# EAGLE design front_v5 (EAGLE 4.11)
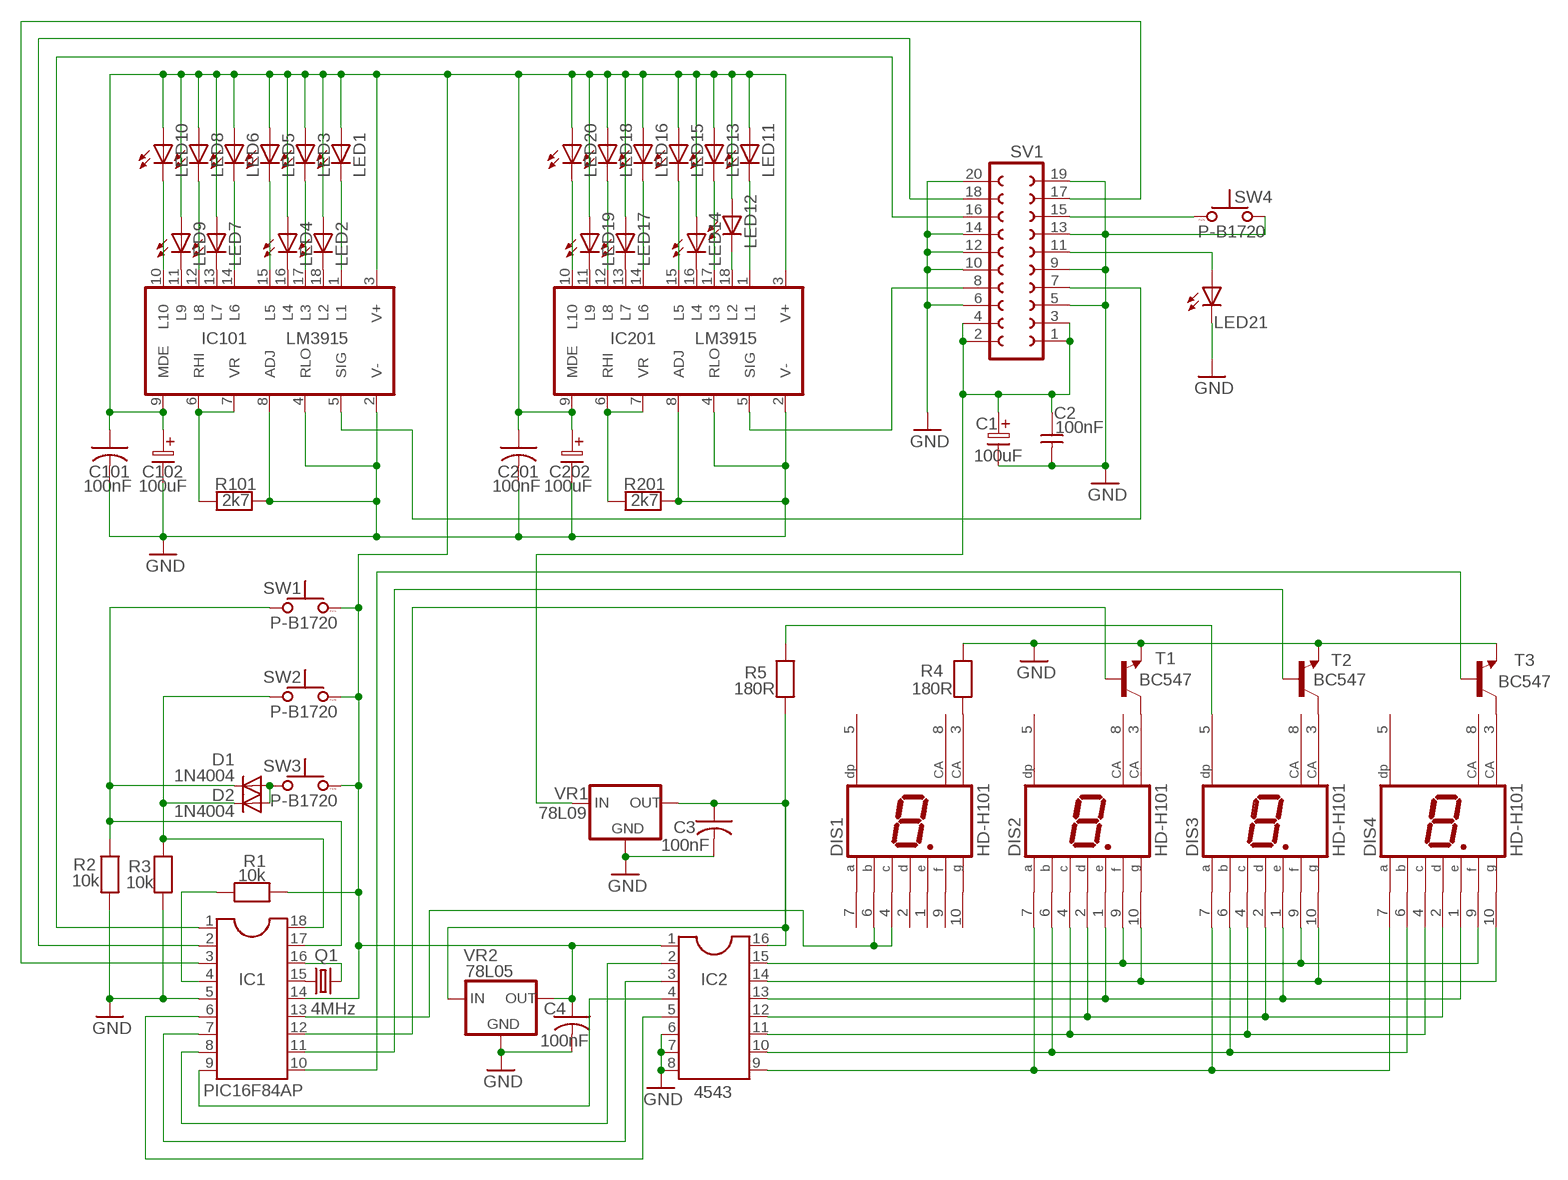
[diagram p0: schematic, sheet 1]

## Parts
C1  100uF  ELC-2,5  [ES-2,5]
C2  100nF  CAPNP-5  [C-5]
C3  100nF  CAP-5  [C-5]
C4  100nF  CAP-5  [C-5]
C101  100nF  CAP-5  [C-5]
C102  100uF  ELC-2,5  [ES-2,5]
C201  100nF  CAP-5  [C-5]
C202  100uF  ELC-2,5  [ES-2,5]
D1  1N4004  [DO41-10]
D2  1N4004  [DO41-10]
DIS1  HD-H101  [HDSP-M]
DIS2  HD-H101  [HDSP-M]
DIS3  HD-H101  [HDSP-M]
DIS4  HD-H101  [HDSP-M]
IC1  PIC16F84AP  DIL18  [DIL18]
IC2  4543  DIL16  [DIL16]
IC101  LM3915  LM3914N  [DIL18]
IC201  LM3915  LM3914N  [DIL18]
LED1  LED5MM  [LED5MM]
LED2  LED5MM  [LED5MM]
LED3  LED5MM  [LED5MM]
LED4  LED5MM  [LED5MM]
LED5  LED5MM  [LED5MM]
LED6  LED5MM  [LED5MM]
LED7  LED5MM  [LED5MM]
LED8  LED5MM  [LED5MM]
LED9  LED5MM  [LED5MM]
LED10  LED5MM  [LED5MM]
LED11  LED5MM  [LED5MM]
LED12  LED5MM  [LED5MM]
LED13  LED5MM  [LED5MM]
LED14  LED5MM  [LED5MM]
LED15  LED5MM  [LED5MM]
LED16  LED5MM  [LED5MM]
LED17  LED5MM  [LED5MM]
LED18  LED5MM  [LED5MM]
LED19  LED5MM  [LED5MM]
LED20  LED5MM  [LED5MM]
LED21  LED5MM  [LED5MM]
Q1  4MHz  CRYTALHC49U-V  [HC49U-V]
R1  10k  RESEU-7,5  [R-7,5]
R2  10k  RESEU-7,5  [R-7,5]
R3  10k  RESEU-7,5  [R-7,5]
R4  180R  RESEU-7,5  [R-7,5]
R5  180R  RESEU-7,5  [R-7,5]
R101  2k7  RESEU-7,5  [R-7,5]
R201  2k7  RESEU-7,5  [R-7,5]
SV1  FE10-2  [FE10-2]
SW1  P-B1720  [P-B1720]
SW2  P-B1720  [P-B1720]
SW3  P-B1720  [P-B1720]
SW4  P-B1720  [P-B1720]
T1  BC547  BC238  [TO92]
T2  BC547  BC238  [TO92]
T3  BC547  BC238  [TO92]
VR1  78L09  78LXX  [78LXX]
VR2  78L05  78LXX  [78LXX]

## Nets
GND: C1.2 C2.2 C3.2 C4.2 C101.2 C102.2 C201.2 C202.2 IC1.5 IC2.6 IC2.7 IC2.8 IC101.2(V-) IC101.4(RLO) IC101.8(ADJ) IC201.2(V-) IC201.4(RLO) IC201.8(ADJ) LED21.K(C) R2.1 R3.1 R4.2 R101.2 R201.2 SV1.5 SV1.6 SV1.9 SV1.10 SV1.12 SV1.13 SV1.14 SV1.19 SV1.20 SW4.2 T1.1(E) T2.1(E) T3.1(E) VR1.GND VR2.GND
N$1: IC1.4 R1.1
N$2: IC1.15 Q1.1
N$3: IC1.16 Q1.2
N$4: DIS1.3(CA) R4.1
N$5: IC1.6 IC2.5
N$6: IC1.7 IC2.3
N$7: IC1.8 IC2.2
N$8: IC1.9 IC2.4
N$9: C3.1 IC2.16 R5.1 VR1.OUT VR2.IN
N$11: LED21.A SV1.11
N$12: C1.1 C2.1 SV1.1 SV1.2 SV1.3 SV1.4 VR1.IN
N$13: DIS2.7(A) DIS3.7(A) DIS4.7(A) IC2.9
N$14: DIS2.6(B) DIS3.6(B) DIS4.6(B) IC2.10
N$15: DIS2.4(C) DIS3.4(C) DIS4.4(C) IC2.11
N$16: DIS2.2(D) DIS3.2(D) DIS4.2(D) IC2.12
N$17: DIS2.1(E) DIS3.1(E) DIS4.1(E) IC2.13
N$18: DIS2.10(G) DIS3.10(G) DIS4.10(G) IC2.14
N$19: DIS2.9(F) DIS3.9(F) DIS4.9(F) IC2.15
N$20: DIS1.4(C) DIS1.6(B) IC1.13
N$21: DIS3.5(DP) R5.2
N$22: DIS2.3(CA) T1.3(C)
N$23: DIS3.3(CA) T2.3(C)
N$24: DIS4.3(CA) T3.3(C)
N$25: IC1.12 T1.2(B)
N$27: IC1.11 T2.2(B)
N$28: IC1.10 T3.2(B)
N$29: SV1.15 SW4.1
N$30: D1.C IC1.17 R2.2 SW1.2
N$31: D2.C IC1.18 R3.2 SW2.2
N$32: IC1.1 SV1.16
N$33: IC1.2 SV1.18
N$34: IC1.3 SV1.17
N$35: IC201.1(L1) LED11.K(C)
N$36: IC101.18(L2) LED2.K(C)
N$37: IC201.17(L3) LED13.K(C)
N$38: IC101.16(L4) LED4.K(C)
N$39: IC201.15(L5) LED15.K(C)
N$40: IC201.14(L6) LED16.K(C)
N$41: IC101.13(L7) LED7.K(C)
N$42: IC201.12(L8) LED18.K(C)
N$43: IC101.11(L9) LED9.K(C)
N$44: IC201.10(L10) LED20.K(C)
N$45: IC201.6(RHI) IC201.7(VR) R201.1
N$47: IC201.16(L4) LED14.K(C)
N$48: IC201.13(L7) LED17.K(C)
N$49: IC201.11(L9) LED19.K(C)
N$50: IC201.5(SIG) SV1.8
N$51: IC101.5(SIG) SV1.7
N$52: IC201.18(L2) LED12.K(C)
N$55: D1.A D2.A SW3.2
N$76: IC101.1(L1) LED1.K(C)
N$80: IC101.17(L3) LED3.K(C)
N$83: IC101.15(L5) LED5.K(C)
N$84: IC101.14(L6) LED6.K(C)
N$86: IC101.12(L8) LED8.K(C)
N$88: IC101.10(L10) LED10.K(C)
N$93: IC101.6(RHI) IC101.7(VR) R101.1
V+: C4.1 C101.1 C102.1 C201.1 C202.1 IC1.14 IC2.1 IC101.3(V+) IC101.9(MDE) IC201.3(V+) IC201.9(MDE) LED1.A LED2.A LED3.A LED4.A LED5.A LED6.A LED7.A LED8.A LED9.A LED10.A LED11.A LED12.A LED13.A LED14.A LED15.A LED16.A LED17.A LED18.A LED19.A LED20.A R1.2 SW1.1 SW2.1 SW3.1 VR2.OUT
Unconnected: DIS1.1(E) DIS1.2(D) DIS1.5(DP) DIS1.7(A) DIS1.8(CA) DIS1.9(F) DIS1.10(G) DIS2.5(DP) DIS2.8(CA) DIS3.8(CA) DIS4.5(DP) DIS4.8(CA) SW1.3 SW1.4 SW2.3 SW2.4 SW3.3 SW3.4 SW4.3 SW4.4

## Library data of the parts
C1 C102 C202 = discrete:ELC-2,5
C2 = discrete:CAPNP-5
C3 C4 C101 C201 = discrete:CAP-5
D1 D2 = diode:1N4004: DIODE
DIS1-DIS4 = display-hp:HD-H101: LED DISPLAY 1-character 7 segment, decimal point right
IC1 = ic-package:DIL18: Dual In Line
IC2 = ic-package:DIL16: Dual In Line
IC101 IC201 = linear:LM3914N: LED DRIVER senses analog voltage levels and drives 10 LEDs
LED1-LED21 = led:LED: LED
Q1 = crystal:CRYTAL: CRYSTAL
R1-R5 R101 R201 = discrete:RESEU-7,5
SV1 = con-lsta:FE10-2: FEMALE HEADER
SW1-SW4 = #PaJa_16:P-B1720: &micro;-tlacitko
T1-T3 = transistor:BC238: NPN TRANSISTOR
VR1 VR2 = v-reg:78LXX: VOLTAGE REGULATOR

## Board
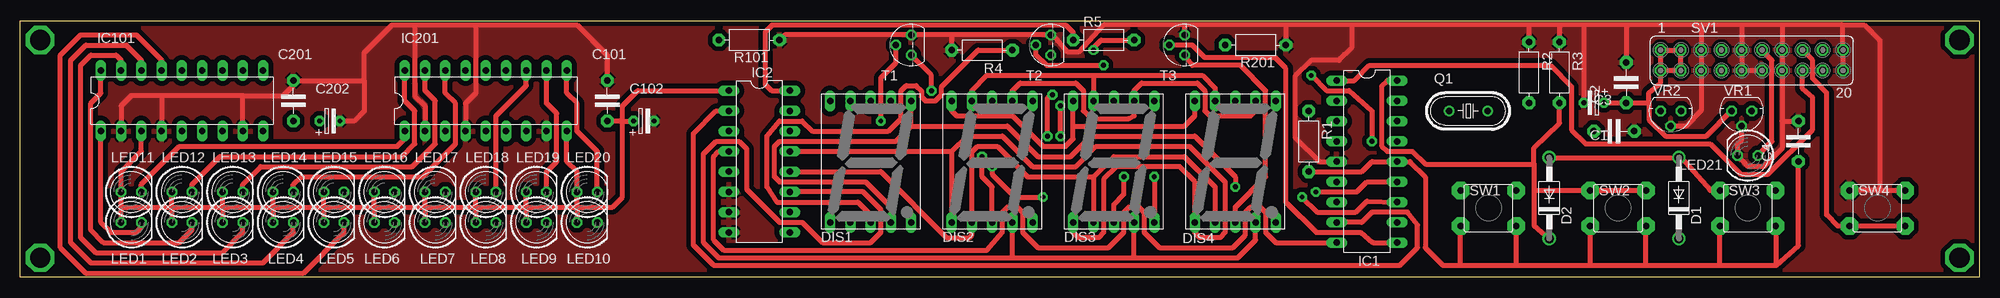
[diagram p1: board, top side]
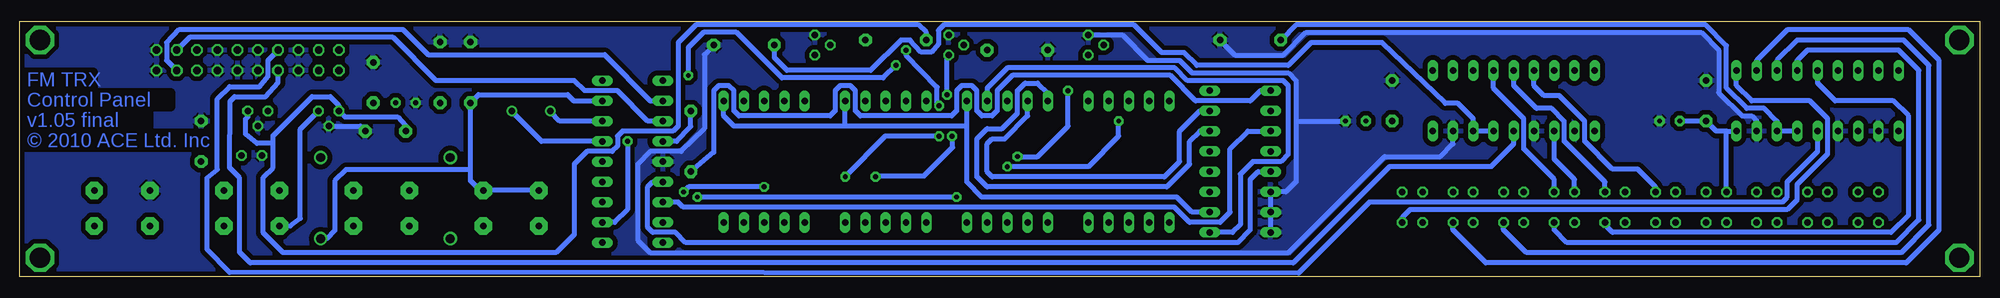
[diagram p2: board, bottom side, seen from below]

Size 245.72 x 32.05 mm. Coordinates in mm from the lower left corner, seen from the top.
Outline: 0,0 245.72,0 245.72,32.05 0,32.05 0,0
Copper layers (1*16): Top 0.035mm / dielectric 1.5mm / Bottom 0.035mm
Design rules "TRIDA5": minimum track width 10mil, minimum drill 24mil, track to track 12mil, track to pad 10mil, pad to pad 11mil, via to via 12mil, smd to smd 12mil, copper to edge 25mil, drill to drill 12mil, minimum pad ring 10mil, minimum via ring 12mil, stop-mask expansion 4mil, vias tented up to drill 0mil, thermal gap 10mil

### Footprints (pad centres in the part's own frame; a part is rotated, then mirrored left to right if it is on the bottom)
ES-2,5 = drill 0.61 pad 1.27 octagon: 1 -1.27,0; 2 1.27,0
C-5 = drill 0.813 pad 1.6 octagon: 1 -2.54,0; 2 2.54,0
DO41-10 = drill 1.118 round: A 5.08,0; C -5.08,0
HDSP-M = drill 0.813 long: 1 -5.08,-7.62; 2 -2.54,-7.62; 3 0,-7.62; 4 2.54,-7.62; 5 5.08,-7.62; 6 5.08,7.62; 7 2.54,7.62; 8 0,7.62; 9 -2.54,7.62; 10 -5.08,7.62
DIL18 = drill 0.813 long: 1 -10.16,-3.81; 2 -7.62,-3.81; 3 -5.08,-3.81; 4 -2.54,-3.81; 5 0,-3.81; 6 2.54,-3.81; 7 5.08,-3.81; 8 7.62,-3.81; 9 10.16,-3.81; 10 10.16,3.81; 11 7.62,3.81; 12 5.08,3.81; 13 2.54,3.81; 14 0,3.81; 15 -2.54,3.81; 16 -5.08,3.81; 17 -7.62,3.81; 18 -10.16,3.81
DIL16 = drill 0.813 long: 1 -8.89,-3.81; 2 -6.35,-3.81; 3 -3.81,-3.81; 4 -1.27,-3.81; 5 1.27,-3.81; 6 3.81,-3.81; 7 6.35,-3.81; 8 8.89,-3.81; 9 8.89,3.81; 10 6.35,3.81; 11 3.81,3.81; 12 1.27,3.81; 13 -1.27,3.81; 14 -3.81,3.81; 15 -6.35,3.81; 16 -8.89,3.81
LED5MM = drill 0.813 octagon: A -1.27,0; K 1.27,0
HC49U-V = drill 0.813 round: 1 -2.413,0; 2 2.413,0
R-7,5 = drill 0.813 pad 1.6 octagon: 1 -3.81,0; 2 3.81,0
FE10-2 = drill 0.914 octagon: 1 -11.43,1.27; 2 -11.43,-1.27; 3 -8.89,1.27; 4 -8.89,-1.27; 5 -6.35,1.27; 6 -6.35,-1.27; 7 -3.81,1.27; 8 -3.81,-1.27; 9 -1.27,1.27; 10 -1.27,-1.27; 11 1.27,1.27; 12 1.27,-1.27; 13 3.81,1.27; 14 3.81,-1.27; 15 6.35,1.27; 16 6.35,-1.27; 17 8.89,1.27; 18 8.89,-1.27; 19 11.43,1.27; 20 11.43,-1.27
P-B1720 = drill 0.813 pad 2.184 octagon: 1 -3.493,-2.223; 2 -3.493,2.223; 3 3.493,-2.223; 4 3.493,2.223
TO92 = drill 0.813 octagon: 1 1.27,0; 2 0,1.905; 3 -1.27,0
78LXX = drill 0.813 octagon: GND 0,1.905; IN 1.27,0; OUT -1.27,0

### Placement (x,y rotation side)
C1  197.35,21.81 180 top
C2  201.42,24.35 90 top
C3  199.89,18.25 0 top
C4  223.01,16.98 90 top
C101  73.66,22.06 90 top
C102  78.23,19.52 0 top
C201  34.29,22.06 90 top
C202  38.86,19.52 0 top
D1  208.02,9.87 90 top
D2  191.76,9.87 90 top
DIS1  106.67,14.44 0 top
DIS2  121.92,14.44 0 top
DIS3  137.15,14.44 0 top
DIS4  152.39,14.44 0 top
IC1  168.9,14.44 270 top
IC2  92.7,14.44 270 top
IC101  20.32,22.06 0 top
IC201  58.41,22.06 0 top
LED1  13.96,6.82 0 top
LED2  20.32,6.82 0 top
LED3  26.66,6.82 0 top
LED4  33.02,6.82 0 top
LED5  39.37,6.82 0 top
LED6  45.72,6.82 0 top
LED7  52.06,6.82 0 top
LED8  58.41,6.82 0 top
LED9  64.77,6.82 0 top
LED10  71.11,6.82 0 top
LED11  13.96,10.63 0 top
LED12  20.32,10.63 0 top
LED13  26.66,10.63 0 top
LED14  33.02,10.63 0 top
LED15  39.37,10.63 0 top
LED16  45.72,10.63 0 top
LED17  52.06,10.63 0 top
LED18  58.41,10.63 0 top
LED19  64.77,10.63 0 top
LED20  71.11,10.63 0 top
LED21  216.66,15.2 180 top
Q1  181.6,20.79 180 top
R1  161.6,16.98 270 top
R2  189.22,25.62 270 top
R3  193.03,25.62 270 top
R4  120.64,28.41 180 top
R5  135.88,29.68 0 top
R101  91.44,29.68 0 top
R201  154.93,29.04 0 top
SV1  217.16,27.14 0 top
SW1  184.14,8.6 0 top
SW2  200.4,8.6 0 top
SW3  216.66,8.6 0 top
SW4  232.91,8.6 0 top
T1  111.75,29.04 90 top
T2  129.28,29.04 90 top
T3  146.04,29.04 90 top
VR1  215.89,20.79 180 top
VR2  207,20.79 180 top

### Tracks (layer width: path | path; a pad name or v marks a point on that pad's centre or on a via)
GND
  Top 0.61: 220.97,31.58 215.89,31.58 | 215.89,31.58 210.81,31.58 | 228.59,31.58 220.97,31.58 | 233.23,10.82 233.23,29.62 231.26,31.58 228.59,31.58 | VR1.GND 215.89,17.17 215.39,16.66 LED21.K 216.72,13.81 218.69,13.81 220.97,16.09 220.97,19.52 | VR2.GND 208.91,18.88 210.81,20.85 SV1.6 SV1.5 210.81,31.58 | 210.81,31.58 201.42,31.58 | 201.42,31.58 196.08,31.58 | 196.08,31.58 193.03,31.58 | 193.03,31.58 189.22,31.58 | 189.22,31.58 167,31.58 | 167,31.58 158.68,31.58 | 158.68,31.58 146.04,31.58 | 146.04,31.58 T3.1 | IC1.5 163,14.44 159.89,17.49 159.89,25.14 161.92,27.14 165.41,27.14 167,28.73 167,31.58 | 146.04,31.58 135.88,31.58 132.71,28.16 131.44,28.16 129.53,30.31 | 129.53,30.31 T2.1 | 129.53,30.31 116.83,30.31 | 116.83,30.31 111.95,30.31 | 111.95,30.31 T1.1 | 189.22,31.58 R2.1 | 193.03,31.58 R3.1 | 116.83,30.31 R4.2 | 220.97,19.52 SV1.14 SV1.13 220.97,31.58 | SV1.10 215.89,25.74 | SV1.10 SV1.9 215.89,31.58 | SV1.20 SV1.19 228.59,31.58 | IC101.2 12.7,21.42 13.96,22.7 17.78,22.7 | 17.78,22.7 IC101.4 | 43.17,24.6 C201.2 34.29,23.96 33.02,22.7 27.94,22.7 | 27.94,22.7 17.78,22.7 | 57.15,31.58 69.84,31.58 73.66,27.77 C101.2 | 49.52,31.58 57.15,31.58 | 49.52,31.58 46.67,31.58 43.17,28.09 43.17,24.6 | IC201.4 55.88,21.74 57.15,23.01 57.15,31.58 | IC201.2 50.8,21.42 49.52,22.7 49.52,31.58 | 158.68,31.58 158.74,31.52 R201.2 | 43.17,24.6 43.17,20.79 41.91,19.52 C202.2 | 111.95,30.31 95.88,30.31 R101.2 | 196.08,31.58 C1.2 | 201.42,31.58 C2.2 | 220.97,19.52 C4.2 | 233.23,10.82 SW4.2 | 233.23,10.82 236.28,10.82 | SV1.10 SV1.12 | IC101.8 27.94,22.7
  Bottom 0.61: 85.72,19.52 85.72,11.9 86.99,10.63 IC2.6 IC2.7 IC2.8 | 85.72,19.52 85.72,24.6 86.67,25.55 98.74,25.55 100.33,27.14 104.33,27.14 107.5,30.31 111.63,30.31 111.75,30.19 T1.1 | IC201.8 66.03,16.66 67.62,15.08 74.61,15.08 86.67,3.01 166.68,3.01 168.27,4.6 168.27,14.12 166.68,15.71 162.81,15.71 159.89,18.57 159.89,27.84 R201.2 | R101.2 93.34,27.77 87.31,27.77 84.45,30.63 34.92,30.63 32.7,28.41 32.7,23.08 29.78,20.15 28.57,20.15 27.94,19.52 IC101.8 | 85.72,19.52 C102.2 | VR2.GND 203,18.88 C3.2
  pour Bottom (isolate 0.61): -0.01,31.97 245.61,31.97 245.61,-0.04 -0.01,-0.04
  pour Top (isolate 0.61): -0.01,31.97 -0.01,0.22 245.61,0.22 245.61,31.97
N$1
  Bottom 0.61: R1.1 161.6,18.82 163.38,16.98 IC1.4
N$2
  Bottom 0.61: IC1.15 180.33,16.98 184.02,20.66 Q1.1
N$3
  Bottom 0.61: IC1.16 178.05,19.52 179.19,20.66 Q1.2
N$4
  Top 0.61: DIS1.3 106.67,7.77 105.09,9.36 94.93,9.36 93.66,11.27 93.66,17.61 95.25,19.52 98.1,19.52 99.37,18.25 108.9,18.25 110.48,19.84 110.48,23.33 111.12,23.96 112.39,23.96 113.03,23.33 113.03,22.57 113.53,22.06 114.8,22.06 115.56,22.82 115.56,23.84 120.14,28.41 R4.1
N$5
  Bottom 0.61: IC2.5 90.48,13.17 91.44,12.22 91.44,5.87 93.02,4.28 162.24,4.28 163.51,5.55 166.36,5.55 167,6.18 167,11.27 166.36,11.9 IC1.6
N$6
  Bottom 0.61: IC1.7 163.19,9.36 162.55,8.73 100.96,8.73 99.06,6.82 95.25,6.82 93.97,8.09 93.97,16.03 91.75,18.25 IC2.3
N$7
  Top 0.61: IC1.8 168.27,6.82 169.54,8.09 173.98,8.09 175.25,6.5 175.25,3.64 173.03,1.42 86.99,1.42 84.45,3.96 84.45,17.93 87.31,20.79 IC2.2
N$8
  Top 0.61: IC1.9 157.47,4.28 156.2,5.55 156.2,8.09 155.57,8.73 154.3,8.73 153.66,8.09 153.66,5.23 152.08,3.64 142.87,3.64 140.96,5.55 140.96,8.09 140.33,8.73 139.06,8.73 138.42,8.09 138.42,5.55 136.52,3.64 127.63,3.64 125.72,5.55 125.72,8.09 125.09,8.73 123.82,8.73 123.19,8.09 123.19,5.55 121.28,3.33 88.26,3.33 86.99,4.6 86.99,15.08 87.62,15.71 IC2.4
N$9
  Top 0.61: R5.1 132.07,30.63 131.09,31.58 94.36,31.58 93.47,30.7 93.47,24.09 94.23,23.33 IC2.16
  Bottom 0.61: 213.99,16.73 213.99,13.68 215.2,12.47 215.2,5.49 212.72,3.01 178.49,3.01 176.21,5.3 176.21,14.12 174.62,15.71 171.44,15.71 170.81,16.34 170.81,17.61 170.17,18.25 163.82,18.25 163.19,18.88 163.19,29.36 160.97,31.58 133.03,31.58 132.07,30.63 R5.1 | VR1.OUT 217.16,20.03 217.42,19.77 217.42,17.87 216.02,16.73 213.99,16.73 | 213.99,16.73 213.99,17.68 209.1,22.57 206.81,22.57 205.8,21.55 205.8,21.49 205.73,21.42 VR2.IN 204.97,20.03 198.37,20.03 197.35,18.95 C3.1
N$10
  Top 0.61: 229.42,6.38 236.41,6.38
N$11
  Top 0.61: SV1.11 219.7,27.14 219.7,16.98 LED21.A
N$12
  Top 0.61: SV1.2 SV1.4 SV1.3 SV1.1 SV1.2 | VR1.IN 211.45,17.61 206.37,17.61 204.27,19.71 204.27,21.81 | 204.27,21.81 204.27,23.08 205.73,24.35 SV1.2 | 204.27,21.81 C2.1 C1.1
N$13
  Top 0.61: DIS4.7 154.93,20.79 154.3,20.15 149.22,20.15 148.58,20.79 148.58,23.33 147.63,24.28 140.65,24.28 139.69,23.33 DIS3.7 139.69,20.15 139.06,19.84 134.3,19.84 133.34,20.79 133.34,23.33 132.39,24.28 125.41,24.28 124.45,23.33 DIS2.7
  Bottom 0.61: IC2.9 93.66,5.55 92.7,6.5 92.7,12.85 91.12,14.44 87.62,14.44 86.67,15.39 86.67,23.96 87.31,24.6 99.31,24.6 100.9,26.19 121.92,26.19 124.45,23.65 DIS2.7
N$14
  Bottom 0.61: DIS4.6 157.47,20.15 156.2,18.88 142.23,18.88 | 142.23,18.88 DIS3.6 | 127,18.88 142.23,18.88 | 127,18.88 DIS2.6 | IC2.10 98.74,8.09 100.64,10 125.09,10 127,11.9 127,18.88
N$15
  Top 0.61: DIS4.4 154.93,4.6 152.71,2.38 139.69,2.38 | 139.69,2.38 DIS3.4 | 124.45,2.38 139.69,2.38 | 124.45,2.38 DIS2.4 | 124.45,2.38 87.62,2.38 85.72,4.28 85.72,15.39 87.31,16.98 90.17,16.98 91.12,16.03 91.12,10.95 95.25,6.82 98.1,6.82 100.64,4.28 106.67,4.28 107.95,5.55 107.95,8.41 105.72,10.63 IC2.11
N$16
  Top 0.61: IC2.12 107.95,13.17 116.2,4.92 119.06,4.92 119.38,5.23 DIS2.2 119.38,15.65 120.07,16.34 122.55,16.34 126.36,12.54 134.61,12.54 | 134.61,12.54 DIS3.2 | 134.61,12.54 137.15,15.08 146.04,15.08 149.85,11.27 DIS4.2
N$17
  Top 0.61: DIS3.1 132.07,5.55 132.71,4.92 135.25,4.92 135.88,5.55 135.88,12.22 137.47,13.81 145.41,13.81 147.31,11.9 DIS4.1 147.31,5.55 147.95,4.92 150.49,4.92 151.12,5.55 151.12,11.9 146.68,16.34 134.93,16.34 132.39,13.81 127,13.81 123.19,17.61 118.74,17.61 116.83,15.71 | 116.83,15.71 DIS2.1 | IC2.13 116.83,15.71
N$18
  Top 0.61: DIS4.10 147.31,20.15 146.04,18.88 132.07,18.88 | 132.07,18.88 DIS3.10 | 132.07,18.88 132.07,17.3 131.12,16.34 128.26,16.34 124.45,20.15 117.47,20.15 116.83,20.79 DIS2.10
  Bottom 0.61: DIS2.10 116.83,23.01 118.11,24.28 119.69,24.28 120.64,23.33 120.64,20.47 122.55,18.57 124.45,18.57 125.72,17.3 125.72,12.54 124.45,11.27 101.91,11.27 99.06,14.12 99.06,16.98 97.78,18.25 IC2.14
N$19
  Top 0.61: DIS4.9 149.85,23.65 148.27,25.23 134.61,25.23 | 134.61,25.23 DIS3.9 | 134.61,25.23 121.28,25.23 119.38,23.33 DIS2.9
  Bottom 0.61: DIS2.9 119.38,20.15 122.23,17.3 123.82,17.3 124.45,16.66 124.45,13.17 123.82,12.54 102.23,12.54 100.33,14.44 100.33,18.25 97.78,20.79 IC2.15
N$20  (via drill 0.61)
  Top 0.61: DIS1.4 109.22,8.73 106.04,11.9 95.25,11.9 94.61,12.54 94.61,16.34 95.25,16.98 109.85,16.98 111.75,18.88 | 111.75,18.88 DIS1.6 | IC1.13 168.9,11.9 167.63,10.63 v162.49,10.63 | v152.39,11.27 152.39,12.54 147.31,17.61 134.3,17.61 131.76,15.08 127.63,15.08 123.82,18.88 111.75,18.88
  Bottom 0.61: v152.39,11.27 161.86,11.27 v162.49,10.63
N$21  (via drill 0.61)
  Top 0.61: v142.23,12.54 DIS3.5 | v134.61,28.41 134.61,28.73 135.57,29.68 R5.2 | v130.46,17.61 v130.46,21.42
  Bottom 0.61: v134.61,28.41 134.61,27.77 130.71,23.77 130.71,21.71 130.3,21.3 v130.46,21.42 | v130.46,17.61 137.22,17.61 v142.23,12.54
N$22  (via drill 0.61)
  Top 0.61: T1.3 114.3,25.23 v114.3,23.33 | DIS2.3 121.92,11.27 120.64,12.54 v120.64,15.08
  Bottom 0.61: v120.64,15.08 118.11,15.08 114.3,18.88 v114.3,23.33
N$23  (via drill 0.61)
  Top 0.61: v128.84,17.61 128.84,22.38 129.28,22.82 v129.47,22.82 | v138.42,12.54 138.42,10.31 137.15,9.04 DIS3.3
  Bottom 0.61: v128.84,17.61 128.84,17.65 128.77,17.58 128.77,16.22 132.33,12.66 138.42,12.66 v138.42,12.54 | T2.3 129.28,27.9 129.47,27.71 v129.47,22.82
N$24
  Top 0.61: T3.3 147,26.5 153.03,26.5 156.2,23.33 156.2,12.54 152.39,8.73 DIS4.3
N$25  (via drill 0.61)
  Top 0.61: T1.2 109.85,26.82 107.95,24.92 v107.95,19.52 | v121.92,13.81 121.92,12.85 124.77,10 v128.26,10 | IC1.12 168.9,9.49 167.51,8.09 162.68,8.09 v160.78,10
  Bottom 0.61: v107.95,19.52 107.95,17.61 111.75,13.81 v121.92,13.81 | v128.26,10 v160.78,10
N$27  (via drill 0.61)
  Top 0.61: v169.54,16.98 169.54,20.79 166.68,23.33 163.82,23.33 v161.92,25.23 | T2.2 127.39,27.84 128.77,26.5 v135.88,26.5
  Bottom 0.61: IC1.11 171.13,6.82 169.54,8.41 v169.54,16.98 | v161.92,25.23 161.92,28.73 160.01,30.63 155.89,30.63 150.17,24.92 137.47,24.92 v135.88,26.5
N$28
  Top 0.61: T3.2 147,29.04 148.58,27.46 156.2,27.46 157.41,27.46 157.47,27.39 158.74,26.12 158.74,9.36 162.55,5.55 168.14,5.55 169.67,4.28 IC1.10
N$29
  Top 0.61: SV1.15 224.78,27.14 224.78,24.85 226.56,23.08 226.56,7.77 227.9,6.38 SW4.1
N$30
  Bottom 0.61: 189.22,13.42 204.85,13.42 206.24,12.03 206.24,5.8 207.26,4.79 D1.C | 189.22,13.42 R2.2 188.21,22.82 177.03,22.82 176.27,22.06 IC1.17 | 189.22,13.42 189.22,12.03 188.02,10.82 SW1.2
N$31
  Top 0.61: 189.86,14.12 189.86,10.82 | 189.86,10.82 189.86,6.44 D2.C | 189.86,14.12 189.86,16.15 193.03,19.27 R3.2 | IC1.18 171.44,24.6 170.81,23.96 170.81,16.34 171.44,15.71 174.62,15.71 176.27,14.12 189.86,14.12 | 189.86,10.82 SW2.2 204.02,10.82
N$32
  Top 0.61: IC1.1 167.32,24.6 169.22,26.5 191.89,26.5 194.56,23.84 194.56,18.44 196.34,16.66 211.96,16.66 215.77,12.85 219.2,12.85 224.78,18.44 224.78,22.44 223.51,23.58 SV1.16
N$33
  Bottom 0.61: IC1.2 166.68,22.06 172.4,27.84 194.56,27.84 197.73,31.01 225.74,31.01 227.32,29.36 227.32,27.14 SV1.18
N$34
  Bottom 0.61: SV1.17 224.47,30 198.94,30 193.54,24.6 176.21,24.6 174.94,23.33 170.81,23.33 167,19.52 IC1.3
N$35
  Top 0.61: LED11.K 15.24,11.58 20,16.34 47.3,16.34 48.26,17.3 IC201.1
N$36
  Top 0.61: LED2.K 21.59,5.87 20,4.28 10.47,4.28 8.88,5.87 8.88,21.74 10.16,23.01 IC101.18
N$37
  Top 0.61: LED13.K 27.94,11.58 30.16,13.81 49.21,13.81 52.06,16.66 52.06,22.06 50.8,23.33 IC201.17
N$38
  Top 0.61: LED4.K 34.29,5.55 30.48,1.74 8.88,1.74 6.34,4.28 6.34,27.14 8.25,29.04 13.33,29.04 15.24,27.14 IC101.16
N$39
  Bottom 0.61: LED15.K 40.63,11.27 42.86,13.49 46.03,13.49 49.52,16.98 49.52,19.52 52.7,22.7 54.61,22.7 55.88,23.96 IC201.15
N$40
  Bottom 0.61: LED16.K 46.98,11.9 52.06,16.98 52.06,19.52 53.65,21.11 55.56,21.11 58.41,23.96 IC201.14
N$41
  Bottom 0.61: IC101.13 22.86,27.14 21.59,28.41 10.16,28.41 7.61,25.87 7.61,7.14 10.47,4.28 51.75,4.28 53.34,5.87 LED7.K
N$42
  Top 0.61: LED18.K 59.69,20.15 63.49,23.96 IC201.12
N$43
  Bottom 0.61: IC101.11 27.94,27.14 24.12,30.95 8.88,30.95 5.08,27.14 5.08,5.87 9.2,1.74 61.91,1.74 66.03,5.87 LED9.K
N$44
  Top 0.61: LED20.K 72.39,15.71 69.84,18.25 69.84,21.74 68.58,23.01 IC201.10
N$45
  Bottom 0.61: R201.1 151.12,27.46 149.54,25.87 139.06,25.87 135.25,29.68 134.11,29.68 132.71,28.16 131.44,28.16 130.52,29.2 130.55,30.89 129.85,31.58 106.04,31.58 102.55,28.09 99.75,28.09 98.17,26.5 86.67,26.5 83.81,29.36 74.92,29.36 66.99,21.74 65.4,21.74 63.49,19.84 IC201.7 IC201.6
N$47
  Top 0.61: LED14.K 34.29,11.58 35.24,12.54 50.48,12.54 54.61,16.66 54.61,21.74 53.34,23.01 IC201.16
N$48
  Bottom 0.61: LED17.K 53.34,12.22 57.15,16.03 57.15,19.84 60.95,23.65 IC201.13
N$49
  Top 0.61: LED19.K 66.03,13.17 67.31,14.44 67.31,20.47 66.03,21.74 IC201.11
N$50
  Bottom 0.61: IC201.5 58.41,16.66 61.27,13.81 73.97,13.81 86.04,1.74 216.85,1.74 218.18,3.07 218.18,12.41 219.45,13.68 219.39,22 218.82,22.57 214.88,22.57 213.35,24.35 SV1.8
N$51
  Bottom 0.61: IC101.5 20.32,15.71 24.12,11.9 24.12,10 24.76,9.36 76.51,9.36 85.4,0.47 219.45,0.53 222.24,3.46 222.24,12.41 220.97,13.42 220.97,22.31 219.45,23.84 215.64,23.84 214.62,25.11 214.62,27.14 SV1.7
N$52
  Top 0.61: LED12.K 21.59,11.58 25.08,15.08 47.94,15.08 49.52,16.66 49.52,20.79 48.26,22.06 IC201.18
N$54  (via drill 2.54)
  other vias: 243.2,29.68
N$55
  Top 0.61: SW3.2 211.96,10.82 208.34,14.95 D1.A D2.A
N$56  (via drill 2.54)
  other vias: 243.2,2.38
N$57  (via drill 2.54)
  other vias: 2.54,2.38
N$58  (via drill 2.54)
  other vias: 2.54,29.68
N$76
  Top 0.61: LED1.K 15.24,6.18 14.6,5.55 11.43,5.55 10.16,6.82 IC101.1
N$80
  Top 0.61: IC101.17 12.7,27.14 12.06,27.77 8.88,27.77 7.61,26.5 7.61,4.92 9.52,3.01 25.39,3.01 27.94,5.55 LED3.K
N$83
  Top 0.61: LED5.K 40.63,5.55 35.55,0.47 8.25,0.47 5.08,3.64 5.08,27.77 7.61,30.31 14.6,30.31 17.78,27.14 IC101.15
N$84
  Bottom 0.61: IC101.14 20.32,24.28 18.09,22.06 10.79,22.06 8.88,20.15 8.88,7.77 11.11,5.55 46.03,5.55 46.98,6.5 LED6.K
N$86
  Bottom 0.61: IC101.12 25.39,27.14 22.86,29.68 9.52,29.68 6.34,26.5 6.34,6.5 9.84,3.01 56.83,3.01 59.69,5.87 LED8.K
N$88
  Bottom 0.61: IC101.10 30.48,23.96 28.57,22.06 21.27,22.06 19.05,19.84 19.05,15.39 22.86,11.58 22.86,9.68 24.12,8.41 71.43,8.41 72.39,7.46 LED10.K
N$93
  Bottom 0.61: R101.1 85.72,31.58 34.35,31.58 31.75,28.98 31.75,23.65 29.21,21.11 26.98,21.11 25.39,19.52 IC101.7 IC101.6
V+
  Top 0.61: 180.65,1.42 178.43,1.42 176.21,3.64 176.21,12.54 174.3,14.44 IC1.14 169.54,14.44 168.27,13.17 R1.2 | 180.65,1.42 187.64,1.42 | 187.64,1.42 196.91,1.42 | 196.91,1.42 203.89,1.42 | 203.89,1.42 213.16,1.42 | 213.16,1.42 220.21,1.42 | LED1.A 12.7,8.73 | 12.7,8.73 LED11.A 12.7,13.17 15.24,15.71 IC101.3 | 12.7,8.73 19.05,8.73 | 19.05,8.73 LED12.A | 19.05,8.73 LED2.A | 19.05,8.73 25.39,8.73 | 25.39,8.73 31.75,8.73 | 31.75,8.73 38.09,8.73 | 38.09,8.73 44.45,8.73 | 44.45,8.73 50.8,8.73 | 50.8,8.73 57.15,8.73 | 57.15,8.73 63.49,8.73 | 63.49,8.73 69.84,8.73 | 69.84,8.73 LED10.A | 63.49,8.73 LED19.A | 63.49,8.73 LED9.A | 57.15,8.73 LED18.A | 57.15,8.73 LED8.A | 50.8,8.73 LED17.A | 50.8,8.73 LED7.A | 44.45,8.73 LED16.A | 44.45,8.73 LED6.A | 38.09,8.73 LED15.A | 38.09,8.73 LED5.A | 31.75,8.73 LED14.A | 31.75,8.73 LED4.A | 25.39,8.73 LED13.A | 25.39,8.73 LED3.A | IC201.9 68.58,14.44 69.84,13.17 LED20.A 69.84,8.73 | 220.21,1.42 223.01,3.9 C4.1 | 180.65,1.42 SW1.1 | 196.91,1.42 SW2.1 | 213.16,1.42 SW3.1 | 220.21,1.42 220.21,6.38 | 203.89,1.42 203.89,6.5 | 187.64,1.42 187.64,6.57 | IC2.1 77.47,23.33 75.56,21.42 75.56,19.52 | 75.56,19.52 75.56,10 74.29,8.73 69.84,8.73 | 75.56,19.52 C101.1 | 75.56,19.52 C102.1
  Bottom 0.61: 31.75,18.25 IC101.9 | LED14.A 31.75,18.25 | LED17.A 50.8,12.22 53.34,14.76 IC201.3 | R1.2 158.74,15.58 158.74,23.33 158.11,23.96 156.84,23.96 156.2,23.33 156.2,20.79 155.57,20.15 144.14,20.15 143.5,20.79 143.5,23.33 142.87,23.96 141.6,23.96 140.96,23.33 140.96,20.79 140.33,20.15 128.9,20.15 128.26,20.79 128.26,23.33 127.63,23.96 126.36,23.96 125.72,23.33 125.72,20.79 125.09,20.15 123.82,20.15 123.19,20.79 123.19,23.33 121.28,25.23 101.47,25.23 98.29,22.06 91.44,22.06 90.17,23.33 IC2.1 | 31.75,18.25 33.02,18.25 C201.1 C202.1 | VR2.OUT 210.56,18.5 210.56,7.33 211.83,6.38 SW3.1

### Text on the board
Bottom: FM TRX | Control Panel | v1.05 final | © 2010 ACE Ltd. Inc
tValues: LEFT | RIGHT | UP | DOWN | APPLY | MODE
